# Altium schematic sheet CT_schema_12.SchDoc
size 274 x 160 mm
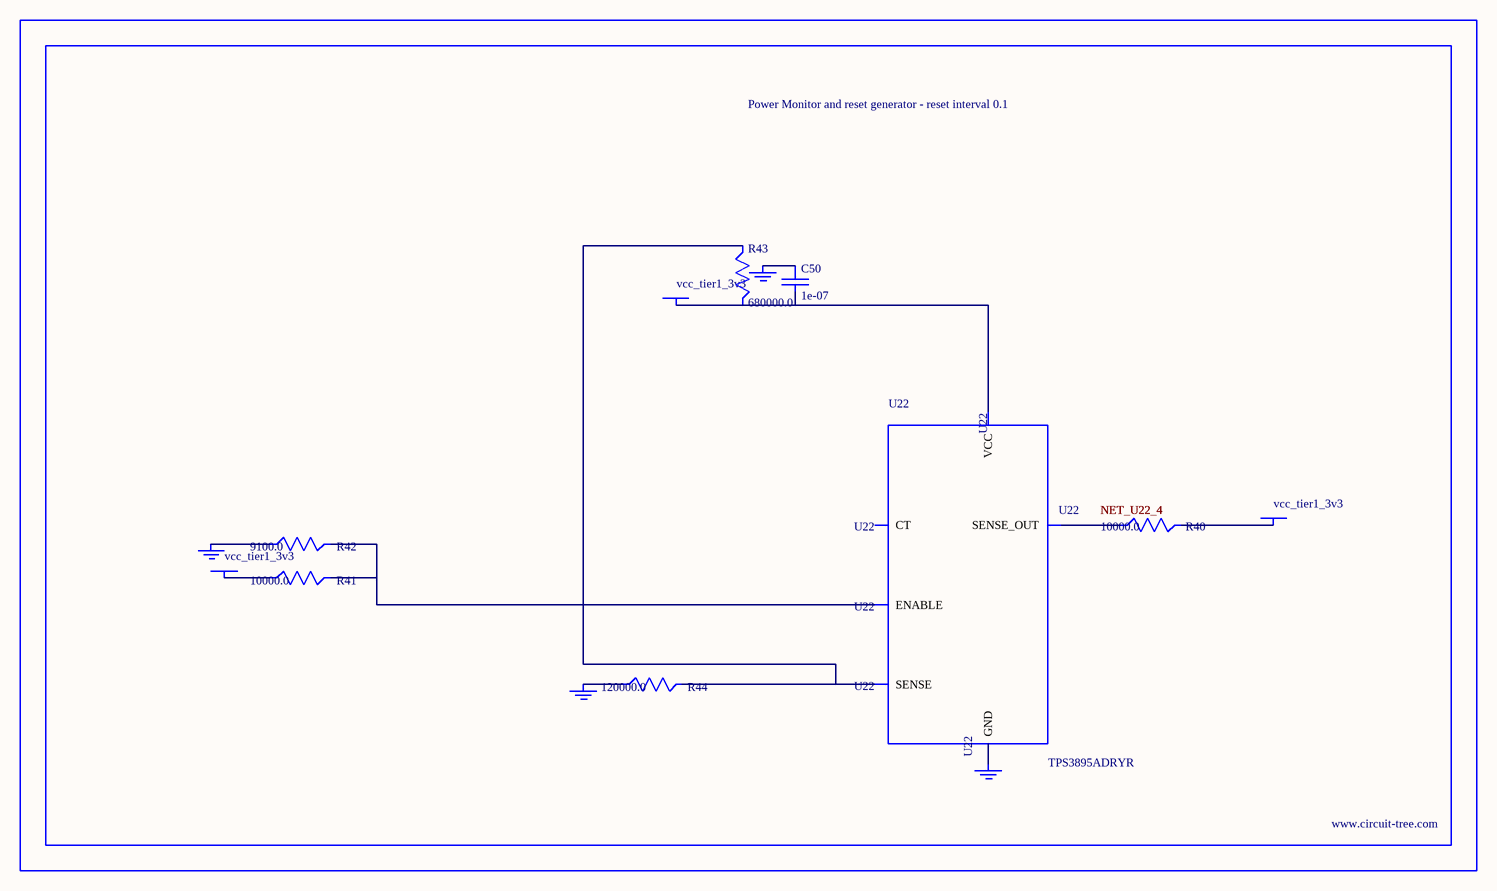
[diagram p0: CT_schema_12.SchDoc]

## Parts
BORDER11  (no value)
C50  1e-07  [C0402]
GND_INSTANCE_11_0  (no value)
GND_INSTANCE_11_1  (no value)
GND_INSTANCE_11_2  (no value)
GND_INSTANCE_11_3  (no value)
POWER_INSTANCE_11_0  vcc_tier1_3v3
POWER_INSTANCE_11_1  vcc_tier1_3v3
POWER_INSTANCE_11_2  vcc_tier1_3v3
R40  10000.0  [R0603]
R41  10000.0  [R0603]
R42  9100.0  [R0603]
R43  680000.0  [R0603]
R44  120000.0  [R0603]
U22  TPS3895ADRYR  [SON-6]

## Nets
NetC50_1: C50.1 GND_INSTANCE_11_2.0(GND)
NetC50_2: C50.2 POWER_INSTANCE_11_2.0(PWR) R43.2 U22.6(VCC)
NetGND_INSTANCE_11_0_0: GND_INSTANCE_11_0.0(GND) R42.1
NetGND_INSTANCE_11_1_0: GND_INSTANCE_11_1.0(GND) R44.1
NetGND_INSTANCE_11_3_0: GND_INSTANCE_11_3.0(GND) U22.2(GND)
NetPOWER_INSTANCE_11_0_0: POWER_INSTANCE_11_0.0(PWR) R41.1
NetPOWER_INSTANCE_11_1_0: POWER_INSTANCE_11_1.0(PWR) R40.2
NetR40_1: R40.1 U22.4(SENSE_OUT)
NetR41_2: R41.2 R42.2 U22.1(ENABLE)
NetR43_1: R43.1 R44.2 U22.3(SENSE)

Not connected (* = marked no-connect by the designer): U22 5(CT)

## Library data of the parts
BORDER11 = BORDER_PAGE11
C50 = C0402C104K3RACTU
GND_INSTANCE_11_0-GND_INSTANCE_11_3 = GND
POWER_INSTANCE_11_0-POWER_INSTANCE_11_2 = PWR
R40 R41 = RC0603JR-0710KL
R42 = RC0603JR-079K1L
R43 = RC0603JR-07680KL
R44 = RC0603JR-07120KL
